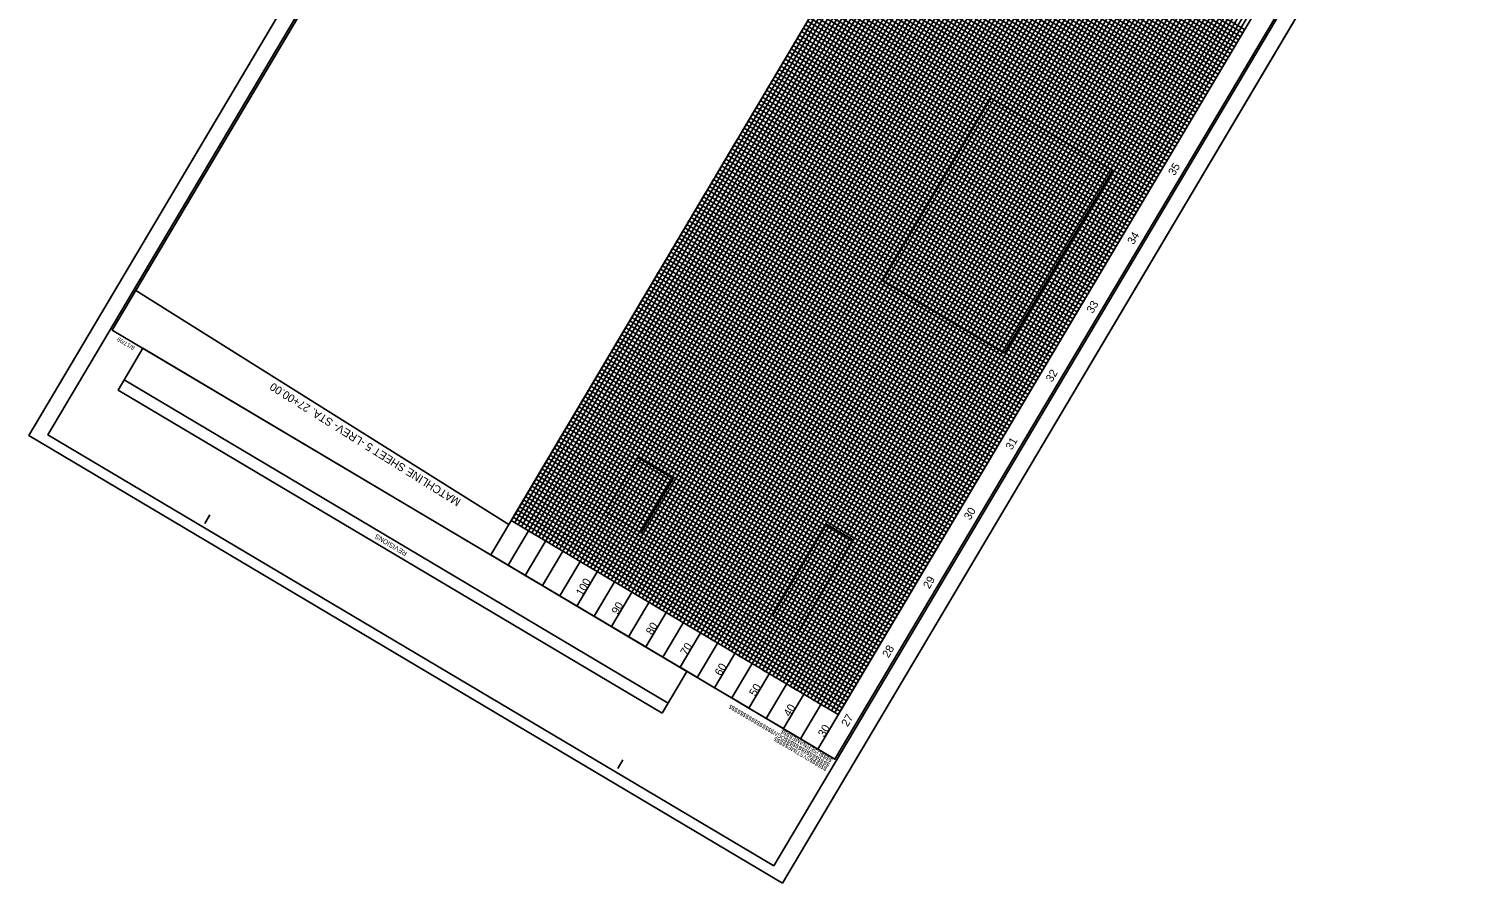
# Model space of a CAD drawing. Extents: x 2138768 to 2143723, y 406633 to 414335.
# Drawn here: x 2140932 to 2142733, y 410238 to 411305 of the extents above; entities that cross this region are included whole.
import ezdxf

# ---------------------------------------------------------------- set-up
doc = ezdxf.new("R2010")
doc.units = 0
for name, color, linetype in [('Exist Vertical Profile Horizontal Axis Label Major', 7, 'Continuous'), ('Exist Vertical Profile Vertical Axis Label', 7, 'Continuous'), ('Prop Dimension', 7, 'Continuous'), ('Prop Dimension Text', 7, 'Continuous'), ('Prop Grid Mask', 7, 'Continuous'), ('Sheet Block Revision CELL', 7, 'Continuous'), ('Sheet Block System Information CELL', 7, 'Continuous'), ('Sheet Clip Boundary CELL', 7, 'Continuous'), ('Sheet Cutting Line CELL', 7, 'Continuous'), ('Sheet DOT Grid CELL', 7, 'Continuous'), ('Sheet Layout Profile Border Port 2', 7, 'Continuous'), ('Sheet Plan And Profile CELL', 7, 'Continuous'), ('Sheet Plot Border Inside CELL', 7, 'Continuous'), ('Sheet Plot Border Outside CELL', 7, 'Continuous'), ('Sheet Profile Grid Major CELL', 7, 'Continuous'), ('Sheet Profile Grid Middle CELL', 7, 'Continuous'), ('Sheet Profile Grid Minor CELL', 7, 'Continuous')]:
    doc.layers.add(name, color=color, linetype=linetype)

msp = doc.modelspace()

# ---------------------------------------------------------------- linework, layer by layer
at = {"layer": 'Prop Dimension'}
msp.add_line((2141532, 410686.1), (2141065.9, 410978.3), dxfattribs=at)
at = {"layer": 'Prop Grid Mask'}
for points in [[(2141998.7, 410990.6), (2142134.1, 411218.7), (2142286.3, 411128.3), (2142150.9, 410900.2)], [(2141697.2, 410675.9), (2141737.4, 410743.6), (2141693.2, 410769.8), (2141653, 410702.2)], [(2141894.2, 410553.3), (2141961.7, 410667), (2141928.8, 410686.6), (2141861.3, 410572.8)]]:
    msp.add_lwpolyline(points, close=True, dxfattribs=at)
at = {"layer": 'Sheet Block Revision CELL'}
msp.add_line((2141731.2, 410463.2), (2141051.3, 410866.8), dxfattribs=at)
msp.add_lwpolyline([(2141723.7, 410450.7), (2141043.8, 410854.2), (2141074.7, 410906.3), (2141754.6, 410502.8)], close=True, dxfattribs=at)
at = {"layer": 'Sheet Block System Information CELL'}
msp.add_line((2141939.5, 410393), (2141939.5, 410393), dxfattribs=at)
at = {"layer": 'Sheet Clip Boundary CELL'}
msp.add_lwpolyline([(2141532, 410686.1), (2141538.9, 410697.6), (2142265.1, 411921.2), (2142261.9, 411923.1), (2142271.9, 411940), (2141951.4, 412130.3), (2141849.3, 411958.2), (2141755.1, 412014.2), (2141652.8, 411841.9), (2141597.8, 411874.5), (2141065.9, 410978.3)], close=True, dxfattribs=at)
at = {"layer": 'Sheet Cutting Line CELL'}
for p, q in [((2141791.5, 412245), (2140932.3, 410797.3)), ((2141873.9, 410238.4), (2142733.2, 411686.1)), ((2140932.3, 410797.3), (2141873.9, 410238.4))]:
    msp.add_line(p, q, dxfattribs=at)
at = {"layer": 'Sheet DOT Grid CELL'}
for p, q in [((2141509.6, 410648.2), (2142275.2, 411938.1)), ((2141552.6, 410622.7), (2142318.2, 411912.6)), ((2141595.6, 410597.2), (2142361.2, 411887.1)), ((2141638.6, 410571.7), (2142404.2, 411861.6)), ((2141681.6, 410546.1), (2142447.2, 411836.1)), ((2141724.5, 410520.6), (2142490.2, 411810.5)), ((2141767.5, 410495.1), (2142533.2, 411785)), ((2141810.5, 410469.6), (2142576.1, 411759.5)), ((2141853.5, 410444.1), (2142619.1, 411734)), ((2141896.5, 410418.5), (2142662.1, 411708.5)), ((2142020, 411508.2), (2142428.4, 411265.7)), ((2141994.4, 411465.2), (2142402.9, 411222.7)), ((2141968.9, 411422.2), (2142377.4, 411179.7)), ((2141943.4, 411379.2), (2142351.9, 411136.7)), ((2141917.9, 411336.2), (2142326.4, 411093.7)), ((2141892.4, 411293.2), (2142300.8, 411050.7)), ((2141866.8, 411250.2), (2142275.3, 411007.7)), ((2141841.3, 411207.2), (2142249.8, 410964.7)), ((2141815.8, 411164.2), (2142224.3, 410921.7)), ((2141790.3, 411121.2), (2142198.8, 410878.8)), ((2141764.8, 411078.2), (2142173.2, 410835.8)), ((2141739.2, 411035.2), (2142147.7, 410792.8)), ((2141713.7, 410992.2), (2142122.2, 410749.8)), ((2141688.2, 410949.2), (2142096.7, 410706.8)), ((2141662.7, 410906.2), (2142071.2, 410663.8)), ((2141637.2, 410863.2), (2142045.6, 410620.8)), ((2141611.6, 410820.2), (2142020.1, 410577.8)), ((2141586.1, 410777.2), (2141994.6, 410534.8)), ((2141560.6, 410734.2), (2141969.1, 410491.8)), ((2141535.1, 410691.2), (2141943.6, 410448.8))]:
    msp.add_line(p, q, dxfattribs=at)
at = {"layer": 'Sheet Layout Profile Border Port 2'}
msp.add_lwpolyline([(2141535.1, 410691.2), (2142249.7, 411895.1), (2142658.1, 411652.7), (2141943.6, 410448.8)], close=True, dxfattribs=at)
at = {"layer": 'Sheet Plan And Profile CELL'}
for p, q in [((2142683.6, 411695.7), (2141918, 410405.8)), ((2141152.1, 410687.7), (2141158.5, 410698.4)), ((2141668.1, 410381.4), (2141674.5, 410392.2)), ((2141939.5, 410393), (2141939.5, 410393)), ((2141939.5, 410393), (2141939.5, 410393)), ((2141939.5, 410393), (2141939.5, 410393)), ((2141939.5, 410393), (2141939.5, 410393)), ((2141939.5, 410393), (2141939.5, 410393))]:
    msp.add_line(p, q, dxfattribs=at)
msp.add_lwpolyline([(2141802.2, 412218.9), (2141036.6, 410929), (2141939.5, 410393), (2142705.1, 411682.9)], close=True, dxfattribs=at)
at = {"layer": 'Sheet Plot Border Inside CELL'}
msp.add_lwpolyline([(2141863.3, 410259.8), (2142713.7, 411692.4), (2141806.4, 412230.9), (2140956.1, 410798.2)], close=True, dxfattribs=at)
at = {"layer": 'Sheet Plot Border Outside CELL'}
msp.add_lwpolyline([(2141873.9, 410238.4), (2142733.2, 411686.1), (2141791.5, 412245), (2140932.3, 410797.3)], close=True, dxfattribs=at)
at = {"layer": 'Sheet Profile Grid Major CELL'}
for points in [[(2141509.6, 410648.2), (2142275.2, 411938.1)], [(2142318.2, 411912.6), (2141552.6, 410622.7), (2141595.6, 410597.2), (2142361.2, 411887.1)], [(2142404.2, 411861.6), (2141638.6, 410571.7), (2141681.6, 410546.1), (2142447.2, 411836.1)], [(2142490.2, 411810.5), (2141724.5, 410520.6), (2141767.5, 410495.1), (2142533.2, 411785)], [(2142576.1, 411759.5), (2141810.5, 410469.6), (2141853.5, 410444.1), (2142619.1, 411734)], [(2142662.1, 411708.5), (2141896.5, 410418.5)], [(2142402.9, 411222.7), (2141994.4, 411465.2), (2142020, 411508.2), (2142428.4, 411265.7)], [(2142351.9, 411136.7), (2141943.4, 411379.2), (2141968.9, 411422.2), (2142377.4, 411179.7)], [(2142300.8, 411050.7), (2141892.4, 411293.2), (2141917.9, 411336.2), (2142326.4, 411093.7)], [(2142249.8, 410964.7), (2141841.3, 411207.2), (2141866.8, 411250.2), (2142275.3, 411007.7)], [(2142198.8, 410878.8), (2141790.3, 411121.2), (2141815.8, 411164.2), (2142224.3, 410921.7)], [(2142147.7, 410792.8), (2141739.2, 411035.2), (2141764.8, 411078.2), (2142173.2, 410835.8)], [(2142096.7, 410706.8), (2141688.2, 410949.2), (2141713.7, 410992.2), (2142122.2, 410749.8)], [(2142045.6, 410620.8), (2141637.2, 410863.2), (2141662.7, 410906.2), (2142071.2, 410663.8)], [(2141994.6, 410534.8), (2141586.1, 410777.2), (2141611.6, 410820.2), (2142020.1, 410577.8)], [(2141943.6, 410448.8), (2141535.1, 410691.2), (2141560.6, 410734.2), (2141969.1, 410491.8)], [(2141509.6, 410648.2), (2141918, 410405.8)]]:
    msp.add_lwpolyline(points, dxfattribs=at)
at = {"layer": 'Sheet Profile Grid Middle CELL'}
for p, q in [((2141531.1, 410635.5), (2142296.7, 411925.4)), ((2142339.7, 411899.9), (2141574.1, 410609.9)), ((2141617.1, 410584.4), (2142382.7, 411874.3)), ((2142425.7, 411848.8), (2141660.1, 410558.9)), ((2141703.1, 410533.4), (2142468.7, 411823.3)), ((2142511.7, 411797.8), (2141746, 410507.9)), ((2141789, 410482.3), (2142554.6, 411772.3)), ((2142597.6, 411746.7), (2141832, 410456.8)), ((2141875, 410431.3), (2142640.6, 411721.2)), ((2141574.1, 410609.9), (2141617.1, 410584.4)), ((2141660.1, 410558.9), (2141703.1, 410533.4)), ((2141746, 410507.9), (2141789, 410482.3)), ((2141832, 410456.8), (2141875, 410431.3))]:
    msp.add_line(p, q, dxfattribs=at)
for points in [[(2142415.7, 411244.2), (2142007.2, 411486.7), (2142032.7, 411529.7), (2142441.2, 411287.2)], [(2142364.6, 411158.2), (2141956.2, 411400.7), (2141981.7, 411443.7), (2142390.2, 411201.2)], [(2142313.6, 411072.2), (2141905.1, 411314.7), (2141930.6, 411357.7), (2142339.1, 411115.2)], [(2142262.6, 410986.2), (2141854.1, 411228.7), (2141879.6, 411271.7), (2142288.1, 411029.2)], [(2142211.5, 410900.3), (2141803, 411142.7), (2141828.6, 411185.7), (2142237, 410943.2)], [(2142160.5, 410814.3), (2141752, 411056.7), (2141777.5, 411099.7), (2142186, 410857.3)], [(2142109.4, 410728.3), (2141701, 410970.7), (2141726.5, 411013.7), (2142135, 410771.3)], [(2142058.4, 410642.3), (2141649.9, 410884.7), (2141675.4, 410927.7), (2142083.9, 410685.3)], [(2142007.4, 410556.3), (2141598.9, 410798.7), (2141624.4, 410841.7), (2142032.9, 410599.3)], [(2141956.3, 410470.3), (2141547.8, 410712.7), (2141573.4, 410755.7), (2141981.8, 410513.3)]]:
    msp.add_lwpolyline(points, dxfattribs=at)
at = {"layer": 'Sheet Profile Grid Minor CELL'}
for points in [[(2142254, 411892.6), (2141539.4, 410688.7)], [(2142262.5, 411887.5), (2141548, 410683.6), (2141543.7, 410686.1), (2142258.3, 411890)], [(2142275.4, 411879.8), (2141560.9, 410675.9), (2141556.6, 410678.5), (2141552.3, 410681), (2142266.8, 411884.9)], [(2142284, 411874.7), (2141569.5, 410670.8), (2141565.2, 410673.4), (2142279.7, 411877.3)], [(2142296.9, 411867.1), (2141582.4, 410663.2), (2141578.1, 410665.7), (2141573.8, 410668.3), (2142288.3, 411872.2)], [(2142305.5, 411862), (2141591, 410658.1), (2141586.7, 410660.6), (2142301.2, 411864.5)], [(2142318.4, 411854.3), (2141603.9, 410650.4), (2141599.6, 410652.9), (2141595.3, 410655.5), (2142309.8, 411859.4)], [(2142327, 411849.2), (2141612.5, 410645.3), (2141608.2, 410647.8), (2142322.7, 411851.8)], [(2141625.4, 410637.6), (2141621.1, 410640.2), (2141616.8, 410642.7), (2142331.3, 411846.6)], [(2142344.2, 411839), (2141629.7, 410635.1), (2141625.4, 410637.6), (2142339.9, 411841.5)], [(2142352.8, 411833.9), (2141638.3, 410630), (2141634, 410632.5), (2142348.5, 411836.4)], [(2142365.7, 411826.2), (2141651.2, 410622.3), (2141646.9, 410624.9), (2142361.4, 411828.8)], [(2142374.3, 411821.1), (2141659.8, 410617.2), (2141655.5, 410619.8), (2142370, 411823.7)], [(2142387.2, 411813.5), (2141672.7, 410609.6), (2141668.4, 410612.1), (2142382.9, 411816)], [(2142395.8, 411808.4), (2141681.3, 410604.5), (2141677, 410607), (2142391.5, 411810.9)], [(2142408.7, 411800.7), (2141694.2, 410596.8), (2141689.9, 410599.4), (2142404.4, 411803.3)], [(2142417.3, 411795.6), (2141702.8, 410591.7), (2141698.5, 410594.2), (2142413, 411798.2)], [(2142430.2, 411788), (2141715.7, 410584), (2141711.4, 410586.6), (2142425.9, 411790.5)], [(2142438.8, 411782.8), (2141724.3, 410578.9), (2141720, 410581.5), (2142434.5, 411785.4)], [(2142451.7, 411775.2), (2141737.2, 410571.3), (2141732.9, 410573.8), (2142447.4, 411777.7)], [(2142460.3, 411770.1), (2141745.8, 410566.2), (2141741.5, 410568.7), (2142456, 411772.6)], [(2142473.2, 411762.4), (2141758.7, 410558.5), (2141754.4, 410561.1), (2142468.9, 411765)], [(2142481.8, 411757.3), (2141767.3, 410553.4), (2141763, 410556), (2142477.5, 411759.9)], [(2142494.7, 411749.7), (2141780.2, 410545.8), (2141775.9, 410548.3), (2142490.4, 411752.2)], [(2142503.3, 411744.6), (2141788.8, 410540.7), (2141784.5, 410543.2), (2142499, 411747.1)], [(2142516.2, 411736.9), (2141801.7, 410533), (2141797.4, 410535.6), (2142511.9, 411739.5)], [(2142524.8, 411731.8), (2141810.3, 410527.9), (2141806, 410530.4), (2142520.5, 411734.4)], [(2142537.7, 411724.1), (2141823.2, 410520.2), (2141818.9, 410522.8), (2142533.4, 411726.7)], [(2142546.3, 411719), (2141831.8, 410515.1), (2141827.5, 410517.7), (2142542, 411721.6)], [(2142559.2, 411711.4), (2141844.7, 410507.5), (2141840.4, 410510), (2142554.9, 411713.9)], [(2142567.8, 411706.3), (2141853.3, 410502.4), (2141849, 410504.9), (2142563.5, 411708.8)], [(2142580.7, 411698.6), (2141866.2, 410494.7), (2141861.9, 410497.3), (2142576.4, 411701.2)], [(2142589.3, 411693.5), (2141874.8, 410489.6), (2141870.5, 410492.2), (2142585, 411696.1)], [(2141887.7, 410482), (2141883.4, 410484.5), (2142597.9, 411688.4)], [(2141939.3, 410451.3), (2142653.8, 411655.2), (2142649.5, 411657.8), (2141935, 410453.9), (2141930.7, 410456.4), (2142645.2, 411660.3), (2142640.9, 411662.9), (2141926.4, 410459), (2141922.1, 410461.5), (2141917.8, 410464.1), (2142632.3, 411668), (2142628, 411670.6), (2141913.5, 410466.6), (2141909.2, 410469.2), (2142623.7, 411673.1), (2142619.4, 411675.7), (2141904.9, 410471.8), (2141900.6, 410474.3), (2141896.3, 410476.9), (2142610.8, 411680.8), (2142606.5, 411683.3), (2141892, 410479.4), (2141887.7, 410482), (2142602.2, 411685.9)], [(2142448.9, 411300.1), (2142040.4, 411542.6), (2142042.9, 411546.9), (2142451.4, 411304.4)], [(2142436.1, 411278.6), (2142027.6, 411521.1), (2142030.2, 411525.4), (2142438.6, 411282.9)], [(2142443.8, 411291.5), (2142035.3, 411534), (2142037.8, 411538.3), (2142446.3, 411295.8)], [(2142431, 411270), (2142022.5, 411512.5), (2142025.1, 411516.8), (2142433.5, 411274.3)], [(2142418.2, 411248.5), (2142009.8, 411491), (2142012.3, 411495.3), (2142420.8, 411252.8)], [(2142423.3, 411257.1), (2142014.9, 411499.6), (2142017.4, 411503.9), (2142425.9, 411261.4)], [(2142405.5, 411227), (2141997, 411469.5), (2141999.6, 411473.8), (2142408, 411231.3)], [(2142410.6, 411235.6), (2142002.1, 411478.1), (2142004.7, 411482.4), (2142413.1, 411239.9)], [(2142392.7, 411205.5), (2141984.2, 411448), (2141986.8, 411452.3), (2142395.3, 411209.8)], [(2142397.8, 411214.1), (2141989.3, 411456.6), (2141991.9, 411460.9), (2142400.4, 411218.4)], [(2142385.1, 411192.6), (2141976.6, 411435.1), (2141979.1, 411439.4), (2142387.6, 411196.9)], [(2142372.3, 411171.1), (2141963.8, 411413.6), (2141966.4, 411417.9), (2142374.8, 411175.4)], [(2142379.9, 411184), (2141971.5, 411426.5), (2141974, 411430.8), (2142382.5, 411188.3)], [(2142359.5, 411149.6), (2141951.1, 411392.1), (2141953.6, 411396.4), (2142362.1, 411153.9)], [(2142367.2, 411162.5), (2141958.7, 411405), (2141961.3, 411409.3), (2142369.7, 411166.8)], [(2142354.4, 411141), (2141946, 411383.5), (2141948.5, 411387.8), (2142357, 411145.3)], [(2142341.7, 411119.5), (2141933.2, 411362), (2141935.8, 411366.3), (2142344.2, 411123.8)], [(2142346.8, 411128.1), (2141938.3, 411370.6), (2141940.9, 411374.9), (2142349.3, 411132.4)], [(2142328.9, 411098), (2141920.4, 411340.5), (2141923, 411344.8), (2142331.5, 411102.3)], [(2142334, 411106.6), (2141925.5, 411349.1), (2141928.1, 411353.4), (2142336.6, 411110.9)], [(2142321.3, 411085.1), (2141912.8, 411327.6), (2141915.3, 411331.9), (2142323.8, 411089.4)], [(2142308.5, 411063.6), (2141900, 411306.1), (2141902.6, 411310.4), (2142311, 411067.9)], [(2142316.1, 411076.5), (2141907.7, 411319), (2141910.2, 411323.3), (2142318.7, 411080.8)], [(2142295.7, 411042.1), (2141887.3, 411284.6), (2141889.8, 411288.9), (2142298.3, 411046.4)], [(2142303.4, 411055), (2141894.9, 411297.5), (2141897.5, 411301.8), (2142305.9, 411059.3)], [(2142290.6, 411033.5), (2141882.2, 411276), (2141884.7, 411280.3), (2142293.2, 411037.8)], [(2142277.9, 411012), (2141869.4, 411254.5), (2141872, 411258.8), (2142280.4, 411016.3)], [(2142283, 411020.6), (2141874.5, 411263.1), (2141877.1, 411267.4), (2142285.5, 411024.9)], [(2142265.1, 410990.5), (2141856.6, 411233), (2141859.2, 411237.3), (2142267.7, 410994.8)], [(2142270.2, 410999.1), (2141861.7, 411241.6), (2141864.3, 411245.9), (2142272.8, 411003.4)], [(2142257.5, 410977.6), (2141849, 411220.1), (2141851.5, 411224.4), (2142260, 410981.9)], [(2142244.7, 410956.1), (2141836.2, 411198.6), (2141838.8, 411202.9), (2142247.2, 410960.4)], [(2142252.3, 410969), (2141843.9, 411211.5), (2141846.4, 411215.8), (2142254.9, 410973.3)], [(2142231.9, 410934.6), (2141823.5, 411177.1), (2141826, 411181.4), (2142234.5, 410938.9)], [(2142239.6, 410947.5), (2141831.1, 411190), (2141833.7, 411194.3), (2142242.1, 410951.8)], [(2142226.8, 410926), (2141818.4, 411168.5), (2141820.9, 411172.8), (2142229.4, 410930.3)], [(2142214.1, 410904.6), (2141805.6, 411147), (2141808.2, 411151.3), (2142216.6, 410908.8)], [(2142219.2, 410913.1), (2141810.7, 411155.6), (2141813.3, 411159.9), (2142221.7, 410917.4)], [(2142201.3, 410883.1), (2141792.8, 411125.5), (2141795.4, 411129.8), (2142203.9, 410887.4)], [(2142206.4, 410891.7), (2141797.9, 411134.1), (2141800.5, 411138.4), (2142209, 410896)], [(2142188.5, 410861.6), (2141780.1, 411104), (2141782.6, 411108.3), (2142191.1, 410865.9)], [(2142193.7, 410870.2), (2141785.2, 411112.6), (2141787.7, 411116.9), (2142196.2, 410874.5)], [(2142180.9, 410848.7), (2141772.4, 411091.1), (2141775, 411095.4), (2142183.4, 410853)], [(2142168.1, 410827.2), (2141759.7, 411069.6), (2141762.2, 411073.9), (2142170.7, 410831.5)], [(2142175.8, 410840.1), (2141767.3, 411082.5), (2141769.9, 411086.8), (2142178.3, 410844.4)], [(2142163, 410818.6), (2141754.6, 411061), (2141757.1, 411065.3), (2142165.6, 410822.9)], [(2142150.3, 410797.1), (2141741.8, 411039.5), (2141744.4, 411043.8), (2142152.8, 410801.4)], [(2142155.4, 410805.7), (2141746.9, 411048.1), (2141749.5, 411052.4), (2142157.9, 410810)], [(2142137.5, 410775.6), (2141729, 411018), (2141731.6, 411022.3), (2142140.1, 410779.9)], [(2142142.6, 410784.2), (2141734.1, 411026.6), (2141736.7, 411030.9), (2142145.2, 410788.5)], [(2142124.7, 410754.1), (2141716.3, 410996.5), (2141718.8, 411000.8), (2142127.3, 410758.4)], [(2142129.9, 410762.7), (2141721.4, 411005.1), (2141723.9, 411009.4), (2142132.4, 410767)], [(2142117.1, 410741.2), (2141708.6, 410983.6), (2141711.2, 410987.9), (2142119.6, 410745.5)], [(2142104.3, 410719.7), (2141695.9, 410962.1), (2141698.4, 410966.4), (2142106.9, 410724)], [(2142112, 410732.6), (2141703.5, 410975), (2141706.1, 410979.3), (2142114.5, 410736.9)], [(2142099.2, 410711.1), (2141690.8, 410953.5), (2141693.3, 410957.8), (2142101.8, 410715.4)], [(2142086.5, 410689.6), (2141678, 410932), (2141680.6, 410936.3), (2142089, 410693.9)], [(2142091.6, 410698.2), (2141683.1, 410940.6), (2141685.7, 410944.9), (2142094.1, 410702.5)], [(2142073.7, 410668.1), (2141665.2, 410910.5), (2141667.8, 410914.8), (2142076.3, 410672.4)], [(2142078.8, 410676.7), (2141670.3, 410919.1), (2141672.9, 410923.4), (2142081.4, 410681)], [(2142060.9, 410646.6), (2141652.5, 410889), (2141655, 410893.3), (2142063.5, 410650.9)], [(2142066.1, 410655.2), (2141657.6, 410897.6), (2141660.1, 410901.9), (2142068.6, 410659.5)], [(2142053.3, 410633.7), (2141644.8, 410876.1), (2141647.4, 410880.4), (2142055.8, 410638)], [(2142040.5, 410612.2), (2141632.1, 410854.6), (2141634.6, 410858.9), (2142043.1, 410616.5)], [(2142048.2, 410625.1), (2141639.7, 410867.5), (2141642.3, 410871.8), (2142050.7, 410629.4)], [(2142035.4, 410603.6), (2141627, 410846), (2141629.5, 410850.3), (2142038, 410607.9)], [(2142022.7, 410582.1), (2141614.2, 410824.5), (2141616.7, 410828.8), (2142025.2, 410586.4)], [(2142027.8, 410590.7), (2141619.3, 410833.1), (2141621.9, 410837.4), (2142030.3, 410595)], [(2142009.9, 410560.6), (2141601.4, 410803), (2141604, 410807.3), (2142012.5, 410564.9)], [(2142015, 410569.2), (2141606.5, 410811.6), (2141609.1, 410815.9), (2142017.6, 410573.5)], [(2141997.1, 410539.1), (2141588.7, 410781.5), (2141591.2, 410785.8), (2141999.7, 410543.4)], [(2142002.3, 410547.7), (2141593.8, 410790.1), (2141596.3, 410794.4), (2142004.8, 410552)], [(2141989.5, 410526.2), (2141581, 410768.6), (2141583.6, 410772.9), (2141992, 410530.5)], [(2141976.7, 410504.7), (2141568.3, 410747.1), (2141570.8, 410751.4), (2141979.3, 410509)], [(2141984.4, 410517.6), (2141575.9, 410760), (2141578.5, 410764.3), (2141986.9, 410521.9)], [(2141964, 410483.2), (2141555.5, 410725.6), (2141558.1, 410729.9), (2141966.5, 410487.5)], [(2141971.6, 410496.1), (2141563.2, 410738.5), (2141565.7, 410742.8), (2141974.2, 410500.4)], [(2141958.9, 410474.6), (2141550.4, 410717), (2141552.9, 410721.3), (2141961.4, 410478.9)], [(2141946.1, 410453.1), (2141537.6, 410695.5), (2141540.2, 410699.8), (2141948.7, 410457.4)], [(2141951.2, 410461.7), (2141542.7, 410704.1), (2141545.3, 410708.4), (2141953.8, 410466)]]:
    msp.add_lwpolyline(points, dxfattribs=at)

# ---------------------------------------------------------------- texts
at = {"layer": 'Exist Vertical Profile Horizontal Axis Label Major'}
for s, p in [('35', (2142363.7, 411121.1)), ('34', (2142312.6, 411035)), ('33', (2142261.6, 410949.1)), ('32', (2142210.7, 410863.3)), ('31', (2142160.4, 410778.5)), ('30', (2142108.4, 410691)), ('29', (2142057.4, 410605.1)), ('28', (2142006.4, 410519)), ('27', (2141955.3, 410432.9))]:
    msp.add_text(s, height=10, rotation=59.3093, dxfattribs=at).set_placement(p)
at = {"layer": 'Exist Vertical Profile Vertical Axis Label'}
for s, p in [('100', (2141623.7, 410596.1)), ('90', (2141668.1, 410573)), ('80', (2141711.1, 410547.5)), ('70', (2141754.1, 410521.9)), ('60', (2141797.1, 410496.4)), ('50', (2141840.1, 410470.9)), ('40', (2141883.1, 410445.4)), ('30', (2141926.1, 410419.9))]:
    msp.add_text(s, height=10, rotation=59.3093, dxfattribs=at).set_placement(p)
at = {"layer": 'Prop Dimension Text'}
msp.add_text('MATCHLINE SHEET 5 -LREV- STA. 27+00.00', height=10, rotation=148.0236, dxfattribs=at).set_placement((2141472.9, 410716.9))
at = {"layer": 'Sheet Block Revision CELL'}
msp.add_text('REVISIONS', height=6, rotation=149.3093, dxfattribs=at).set_placement((2141405.6, 410651.7))
at = {"layer": 'Sheet Block System Information CELL'}
for s, p in [('$$$$$$$$$$$$$$$$DGN$$$$$$$$$$$$$$$$', (2141933.6, 410387.7)), ('$$$$USERNAME$$$$', (2141936.9, 410393.3)), ('$$$$$$SYSTIME$$$$$', (2141930.5, 410382.5))]:
    msp.add_text(s, height=5.25, rotation=149.3093, dxfattribs=at).set_placement(p)
at = {"layer": 'Sheet Plan And Profile CELL'}
msp.add_text('8/17/99', height=5.25, rotation=149.3093, dxfattribs=at).set_placement((2141065.2, 410908.2))

doc.saveas('drawing.dxf')
